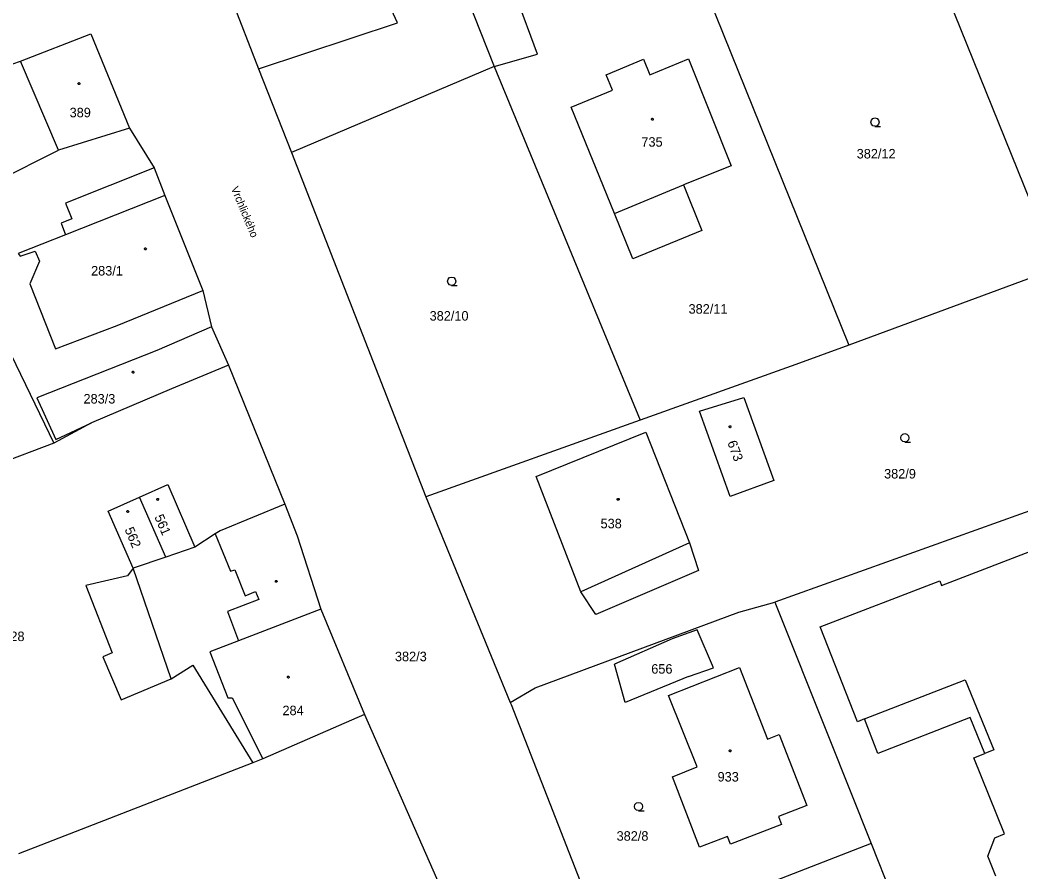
# Model space of a CAD drawing. Extents: x -757994 to -755874, y -1047691 to -1046119.
# Drawn here: x -757748.9 to -757659.5, y -1047146.4 to -1047070.2 of the extents above; entities that cross this region are included whole.
import ezdxf

# ---------------------------------------------------------------- set-up
doc = ezdxf.new("R2010")
doc.units = 0
doc.layers.add('katastrální mapa', color=7, linetype='Continuous')

msp = doc.modelspace()

# ---------------------------------------------------------------- linework, layer by layer
at = {"layer": 'katastrální mapa'}
for p, q in [((-757689.95, -1047061.83), (-757674.85, -1047099.28)), ((-757667.17, -1047065.29), (-757656.22, -1047092.42)), ((-757730.75, -1047066.49), (-757727.6, -1047074.6)), ((-757702.67, -1047073.29), (-757705.17, -1047066.49)), ((-757709.33, -1047067.33), (-757706.55, -1047074.4)), ((-757715.2, -1047070.5), (-757716.4, -1047067.8)), ((-757727.6, -1047074.6), (-757715.2, -1047070.5)), ((-757748.9, -1047073.9), (-757742.59, -1047071.48)), ((-757742.59, -1047071.48), (-757739.13, -1047079.89)), ((-757706.55, -1047074.4), (-757702.67, -1047073.29)), ((-757771.53, -1047081.94), (-757748.9, -1047073.9)), ((-757745.49, -1047081.86), (-757748.9, -1047073.9)), ((-757706.55, -1047074.4), (-757724.67, -1047082.08)), ((-757706.55, -1047074.4), (-757693.5, -1047106)), ((-757727.6, -1047074.6), (-757724.67, -1047082.08)), ((-757739.13, -1047079.89), (-757745.49, -1047081.86)), ((-757739.13, -1047079.89), (-757736.94, -1047083.45)), ((-757753.39, -1047085.83), (-757745.49, -1047081.86)), ((-757724.67, -1047082.08), (-757712.64, -1047112.85)), ((-757736.94, -1047083.45), (-757744.86, -1047086.59)), ((-757736.94, -1047083.45), (-757735.97, -1047085.91)), ((-757695.79, -1047087.54), (-757689.63, -1047084.96)), ((-757735.97, -1047085.91), (-757744.85, -1047089.42)), ((-757735.97, -1047085.91), (-757732.6, -1047094.42)), ((-757744.86, -1047086.59), (-757744.3, -1047088.01)), ((-757744.3, -1047088.01), (-757745.25, -1047088.39)), ((-757745.25, -1047088.39), (-757744.85, -1047089.42)), ((-757744.85, -1047089.42), (-757749.09, -1047091.09)), ((-757656.22, -1047092.42), (-757674.85, -1047099.28)), ((-757732.6, -1047094.42), (-757731.82, -1047097.67)), ((-757731.82, -1047097.67), (-757730.28, -1047101.07)), ((-757674.85, -1047099.28), (-757679.57, -1047101.02)), ((-757749.71, -1047100.17), (-757745.9, -1047108.05)), ((-757730.28, -1047101.07), (-757735.4, -1047103.19)), ((-757730.28, -1047101.07), (-757725.27, -1047113.51)), ((-757679.57, -1047101.02), (-757693.5, -1047106)), ((-757735.4, -1047103.19), (-757742.53, -1047106.25)), ((-757688.19, -1047105.18), (-757684.23, -1047103.96)), ((-757684.23, -1047103.96), (-757681.56, -1047111.38)), ((-757685.44, -1047112.83), (-757688.19, -1047105.18)), ((-757742.53, -1047106.25), (-757745.9, -1047108.05)), ((-757693.5, -1047106), (-757712.64, -1047112.85)), ((-757702.8, -1047111.02), (-757692.98, -1047107.06)), ((-757692.98, -1047107.06), (-757689.07, -1047116.96)), ((-757745.9, -1047108.05), (-757760.59, -1047113.58)), ((-757647.11, -1047109.96), (-757681.45, -1047122.25)), ((-757698.81, -1047121.33), (-757702.8, -1047111.02)), ((-757738.24, -1047112.88), (-757735.71, -1047111.75)), ((-757735.71, -1047111.75), (-757733.3, -1047117.34)), ((-757681.56, -1047111.38), (-757685.44, -1047112.83)), ((-757741.05, -1047114.13), (-757738.24, -1047112.88)), ((-757735.9, -1047118.23), (-757738.24, -1047112.88)), ((-757712.64, -1047112.85), (-757705.11, -1047131.23)), ((-757725.27, -1047113.51), (-757731.05, -1047115.89)), ((-757725.27, -1047113.51), (-757724.15, -1047116.33)), ((-757738.81, -1047119.23), (-757741.05, -1047114.13)), ((-757731.47, -1047116.16), (-757733.3, -1047117.34)), ((-757731.05, -1047115.89), (-757731.47, -1047116.16)), ((-757724.15, -1047116.33), (-757722.05, -1047122.89)), ((-757666.56, -1047120.76), (-757655.24, -1047116.41)), ((-757733.3, -1047117.34), (-757735.9, -1047118.23)), ((-757689.07, -1047116.96), (-757698.81, -1047121.33)), ((-757689.07, -1047116.96), (-757688.29, -1047119.44)), ((-757735.9, -1047118.23), (-757738.81, -1047119.23)), ((-757738.81, -1047119.23), (-757739.31, -1047119.9)), ((-757735.42, -1047129.12), (-757738.81, -1047119.23)), ((-757739.31, -1047119.9), (-757743.05, -1047120.78)), ((-757688.29, -1047119.44), (-757697.46, -1047123.37)), ((-757743.05, -1047120.78), (-757740.69, -1047126.78)), ((-757677.39, -1047124.47), (-757666.71, -1047120.36)), ((-757666.71, -1047120.36), (-757666.56, -1047120.76)), ((-757697.46, -1047123.37), (-757698.81, -1047121.33)), ((-757684.67, -1047123.15), (-757681.45, -1047122.25)), ((-757681.45, -1047122.25), (-757676.66, -1047134.27)), ((-757722.05, -1047122.89), (-757729.4, -1047125.71)), ((-757722.05, -1047122.89), (-757718.14, -1047132.3)), ((-757702.87, -1047129.91), (-757684.67, -1047123.15)), ((-757674.08, -1047132.95), (-757677.39, -1047124.47)), ((-757688.4, -1047124.74), (-757690.63, -1047125.54)), ((-757686.94, -1047128.13), (-757688.4, -1047124.74)), ((-757729.4, -1047125.71), (-757731.95, -1047126.69)), ((-757690.63, -1047125.54), (-757695.8, -1047127.8)), ((-757740.69, -1047126.78), (-757741.52, -1047127.14)), ((-757741.52, -1047127.14), (-757739.89, -1047131)), ((-757731.95, -1047126.69), (-757730.35, -1047130.81)), ((-757735.42, -1047129.12), (-757733.47, -1047127.88)), ((-757733.47, -1047127.88), (-757728.11, -1047136.61)), ((-757694.82, -1047131.23), (-757695.8, -1047127.8)), ((-757690.95, -1047130.6), (-757684.61, -1047128.11)), ((-757689.16, -1047128.91), (-757686.94, -1047128.13)), ((-757684.61, -1047128.11), (-757682.12, -1047134.51)), ((-757689.16, -1047128.91), (-757694.82, -1047131.23)), ((-757739.89, -1047131), (-757735.42, -1047129.12)), ((-757705.11, -1047131.23), (-757702.87, -1047129.91)), ((-757673.43, -1047132.7), (-757664.43, -1047129.2)), ((-757664.43, -1047129.2), (-757661.89, -1047135.47)), ((-757730.35, -1047130.81), (-757729.95, -1047130.8)), ((-757729.95, -1047130.8), (-757727.22, -1047136.26)), ((-757688.41, -1047136.99), (-757690.95, -1047130.6)), ((-757705.11, -1047131.23), (-757705.03, -1047131.42)), ((-757705.03, -1047131.42), (-757696.57, -1047153.02)), ((-757718.14, -1047132.3), (-757727.22, -1047136.26)), ((-757718.14, -1047132.3), (-757697.55, -1047178.97)), ((-757664.01, -1047132.57), (-757672.25, -1047135.8)), ((-757662.67, -1047135.78), (-757664.01, -1047132.57)), ((-757673.43, -1047132.7), (-757674.08, -1047132.95)), ((-757672.25, -1047135.8), (-757673.43, -1047132.7)), ((-757682.12, -1047134.51), (-757681.08, -1047134.08)), ((-757681.08, -1047134.08), (-757678.61, -1047140.42)), ((-757676.66, -1047134.27), (-757672.84, -1047143.83)), ((-757663.67, -1047136.18), (-757662.67, -1047135.78)), ((-757660.92, -1047142.95), (-757663.67, -1047136.18)), ((-757661.89, -1047135.47), (-757662.67, -1047135.78)), ((-757728.11, -1047136.61), (-757749.07, -1047144.74)), ((-757727.22, -1047136.26), (-757728.11, -1047136.61)), ((-757690.61, -1047137.88), (-757688.41, -1047136.99)), ((-757688.19, -1047144.16), (-757690.61, -1047137.88)), ((-757678.61, -1047140.42), (-757681.13, -1047141.43)), ((-757681.13, -1047141.43), (-757680.85, -1047142.13)), ((-757680.85, -1047142.13), (-757685.42, -1047143.9)), ((-757685.69, -1047143.2), (-757688.19, -1047144.16)), ((-757685.42, -1047143.9), (-757685.69, -1047143.2)), ((-757662.41, -1047144.95), (-757661.8, -1047143.31)), ((-757661.8, -1047143.31), (-757660.92, -1047142.95)), ((-757672.84, -1047143.83), (-757696.57, -1047153.02)), ((-757672.84, -1047143.83), (-757664.22, -1047165.51)), ((-757661.71, -1047146.76), (-757662.41, -1047144.95))]:
    msp.add_line(p, q, dxfattribs=at)
for points in [[(-757695.79, -1047087.54), (-757699.67, -1047078.02), (-757695.97, -1047076.51), (-757696.54, -1047075.13), (-757693.19, -1047073.74), (-757692.62, -1047075.13), (-757689.17, -1047073.71)], [(-757689.17, -1047073.71), (-757685.36, -1047083.26), (-757689.63, -1047084.96)], [(-757672.5, -1047079.73), (-757672.69, -1047079.68), (-757672.825, -1047079.545), (-757672.875, -1047079.36), (-757672.825, -1047079.175), (-757672.69, -1047079.04), (-757672.505, -1047078.99), (-757672.32, -1047079.04), (-757672.185, -1047079.175), (-757672.135, -1047079.365), (-757672.185, -1047079.555), (-757672.32, -1047079.69), (-757672.51, -1047079.74), (-757672.01, -1047079.74)], [(-757689.63, -1047084.96), (-757687.99, -1047089.05), (-757694.16, -1047091.58), (-757695.79, -1047087.54)], [(-757749.09, -1047091.09), (-757748.93, -1047091.35), (-757747.56, -1047090.89), (-757747.18, -1047091.79), (-757748.04, -1047093.8), (-757745.75, -1047099.63), (-757740.25, -1047097.54), (-757732.6, -1047094.42)], [(-757710.34, -1047093.95), (-757710.53, -1047093.9), (-757710.665, -1047093.765), (-757710.715, -1047093.58), (-757710.665, -1047093.395), (-757710.53, -1047093.26), (-757710.345, -1047093.21), (-757710.16, -1047093.26), (-757710.025, -1047093.395), (-757709.975, -1047093.585), (-757710.025, -1047093.775), (-757710.16, -1047093.91), (-757710.35, -1047093.96), (-757709.85, -1047093.96)], [(-757731.82, -1047097.67), (-757736.7, -1047099.78), (-757747.42, -1047104.01), (-757745.73, -1047107.71), (-757742.53, -1047106.25)], [(-757669.83, -1047107.94), (-757670.02, -1047107.89), (-757670.155, -1047107.755), (-757670.205, -1047107.57), (-757670.155, -1047107.385), (-757670.02, -1047107.25), (-757669.835, -1047107.2), (-757669.65, -1047107.25), (-757669.515, -1047107.385), (-757669.465, -1047107.575), (-757669.515, -1047107.765), (-757669.65, -1047107.9), (-757669.84, -1047107.95), (-757669.34, -1047107.95)], [(-757731.47, -1047116.16), (-757730.1, -1047119.5), (-757729.73, -1047119.37), (-757728.81, -1047121.69), (-757727.87, -1047121.3), (-757727.59, -1047122.02), (-757730.37, -1047123.1), (-757729.4, -1047125.71)], [(-757693.64, -1047140.89), (-757693.83, -1047140.84), (-757693.965, -1047140.705), (-757694.015, -1047140.52), (-757693.965, -1047140.335), (-757693.83, -1047140.2), (-757693.645, -1047140.15), (-757693.46, -1047140.2), (-757693.325, -1047140.335), (-757693.275, -1047140.525), (-757693.325, -1047140.715), (-757693.46, -1047140.85), (-757693.65, -1047140.9), (-757693.15, -1047140.9)]]:
    msp.add_lwpolyline(points, dxfattribs=at)
for points in [[(-757743.67, -1047075.835), (-757743.62, -1047075.845), (-757743.595, -1047075.89), (-757743.585, -1047075.92), (-757743.595, -1047075.965), (-757743.635, -1047076), (-757743.67, -1047076.005), (-757743.715, -1047075.99), (-757743.745, -1047075.96), (-757743.755, -1047075.92), (-757743.745, -1047075.875), (-757743.705, -1047075.84)], [(-757692.41, -1047079.015), (-757692.36, -1047079.025), (-757692.335, -1047079.07), (-757692.325, -1047079.1), (-757692.335, -1047079.145), (-757692.375, -1047079.18), (-757692.41, -1047079.185), (-757692.455, -1047079.17), (-757692.485, -1047079.14), (-757692.495, -1047079.1), (-757692.485, -1047079.055), (-757692.445, -1047079.02)], [(-757737.72, -1047090.605), (-757737.67, -1047090.615), (-757737.645, -1047090.66), (-757737.635, -1047090.69), (-757737.645, -1047090.735), (-757737.685, -1047090.77), (-757737.72, -1047090.775), (-757737.765, -1047090.76), (-757737.795, -1047090.73), (-757737.805, -1047090.69), (-757737.795, -1047090.645), (-757737.755, -1047090.61)], [(-757738.82, -1047101.625), (-757738.77, -1047101.635), (-757738.745, -1047101.68), (-757738.735, -1047101.71), (-757738.745, -1047101.755), (-757738.785, -1047101.79), (-757738.82, -1047101.795), (-757738.865, -1047101.78), (-757738.895, -1047101.75), (-757738.905, -1047101.71), (-757738.895, -1047101.665), (-757738.855, -1047101.63)], [(-757685.45, -1047106.505), (-757685.4, -1047106.515), (-757685.375, -1047106.56), (-757685.365, -1047106.59), (-757685.375, -1047106.635), (-757685.415, -1047106.67), (-757685.45, -1047106.675), (-757685.495, -1047106.66), (-757685.525, -1047106.63), (-757685.535, -1047106.59), (-757685.525, -1047106.545), (-757685.485, -1047106.51)], [(-757695.46, -1047112.985), (-757695.41, -1047112.995), (-757695.385, -1047113.04), (-757695.375, -1047113.07), (-757695.385, -1047113.115), (-757695.425, -1047113.15), (-757695.46, -1047113.155), (-757695.505, -1047113.14), (-757695.535, -1047113.11), (-757695.545, -1047113.07), (-757695.535, -1047113.025), (-757695.495, -1047112.99)], [(-757736.61, -1047112.995), (-757736.56, -1047113.005), (-757736.535, -1047113.05), (-757736.525, -1047113.08), (-757736.535, -1047113.125), (-757736.575, -1047113.16), (-757736.61, -1047113.165), (-757736.655, -1047113.15), (-757736.685, -1047113.12), (-757736.695, -1047113.08), (-757736.685, -1047113.035), (-757736.645, -1047113)], [(-757739.3, -1047114.075), (-757739.25, -1047114.085), (-757739.225, -1047114.13), (-757739.215, -1047114.16), (-757739.225, -1047114.205), (-757739.265, -1047114.24), (-757739.3, -1047114.245), (-757739.345, -1047114.23), (-757739.375, -1047114.2), (-757739.385, -1047114.16), (-757739.375, -1047114.115), (-757739.335, -1047114.08)], [(-757725.985, -1047120.315), (-757725.94, -1047120.39), (-757725.985, -1047120.465), (-757726.075, -1047120.465), (-757726.12, -1047120.39), (-757726.075, -1047120.315)], [(-757724.94, -1047128.875), (-757724.89, -1047128.885), (-757724.865, -1047128.93), (-757724.855, -1047128.96), (-757724.865, -1047129.005), (-757724.905, -1047129.04), (-757724.94, -1047129.045), (-757724.985, -1047129.03), (-757725.015, -1047129), (-757725.025, -1047128.96), (-757725.015, -1047128.915), (-757724.975, -1047128.88)], [(-757685.45, -1047135.465), (-757685.4, -1047135.475), (-757685.375, -1047135.52), (-757685.365, -1047135.55), (-757685.375, -1047135.595), (-757685.415, -1047135.63), (-757685.45, -1047135.635), (-757685.495, -1047135.62), (-757685.525, -1047135.59), (-757685.535, -1047135.55), (-757685.525, -1047135.505), (-757685.485, -1047135.47)]]:
    msp.add_lwpolyline(points, close=True, dxfattribs=at)

# ---------------------------------------------------------------- texts
for s, p in [('389', (-757744.494, -1047078.93)), ('735', (-757693.384, -1047081.56)), ('382/12', (-757674.138, -1047082.61)), ('283/1', (-757742.576, -1047093.07)), ('382/11', (-757689.167, -1047096.48)), ('382/10', (-757712.314, -1047097.1)), ('283/3', (-757743.254, -1047104.51)), ('382/9', (-757671.69, -1047111.21)), ('538', (-757697.034, -1047115.66)), ('382/28', (-757752.002, -1047125.74)), ('382/3', (-757715.414, -1047127.54)), ('656', (-757692.501, -1047128.65)), ('284', (-757725.467, -1047132.36)), ('933', (-757686.574, -1047138.29)), ('382/8', (-757695.6, -1047143.58))]:
    msp.add_text(s, height=0.85, dxfattribs=at).set_placement(p)
for s, height, rotation, p in [('Vrchlického', 0.7, 292.55225, (-757730.091, -1047085.284)), ('673', 0.85, 290.4896, (-757685.718, -1047107.987)), ('561', 0.85, 293.1825, (-757736.935, -1047114.63)), ('562', 0.85, 292.89602, (-757739.594, -1047115.764))]:
    msp.add_text(s, height=height, rotation=rotation, dxfattribs=at).set_placement(p)

doc.saveas('drawing.dxf')
